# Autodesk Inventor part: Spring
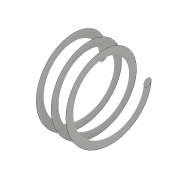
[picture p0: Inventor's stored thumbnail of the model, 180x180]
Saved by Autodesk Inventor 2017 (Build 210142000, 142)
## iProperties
Part Number: Spring
Material: 一般
Document SubType Name: Modeling
Designer: kyushu-hep
Density: 1 g/cm^3
Appearance: 既定
Author: kyushu-hep
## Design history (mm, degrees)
sketch "スケッチ3"
  geometry: C1 r 0.5 at (4.75, 0); 1 further point
  constraints: 1 centre point
  dimensions: "d10" = 1 diameter of C1; "d11" = 4.75 distance of C1.centre point (0, 0)
sketch "スケッチ4"
  geometry: L1 (0, 0)-(7, 0)
  constraints: 2 end point, 1 horizontal
  dimensions: "d12" = 7 distance of L1.start L1.end
feature "コイル2" sketch "スケッチ3", "スケッチ4" pitch "d13" = 2; turns "d15" = 3; dims "d14" = 10, "d16" = 0, angle "d17" = 90 deg, angle "d18" = 90 deg, "d19" = 0, "d20" = 0
node "ソリッド2"
